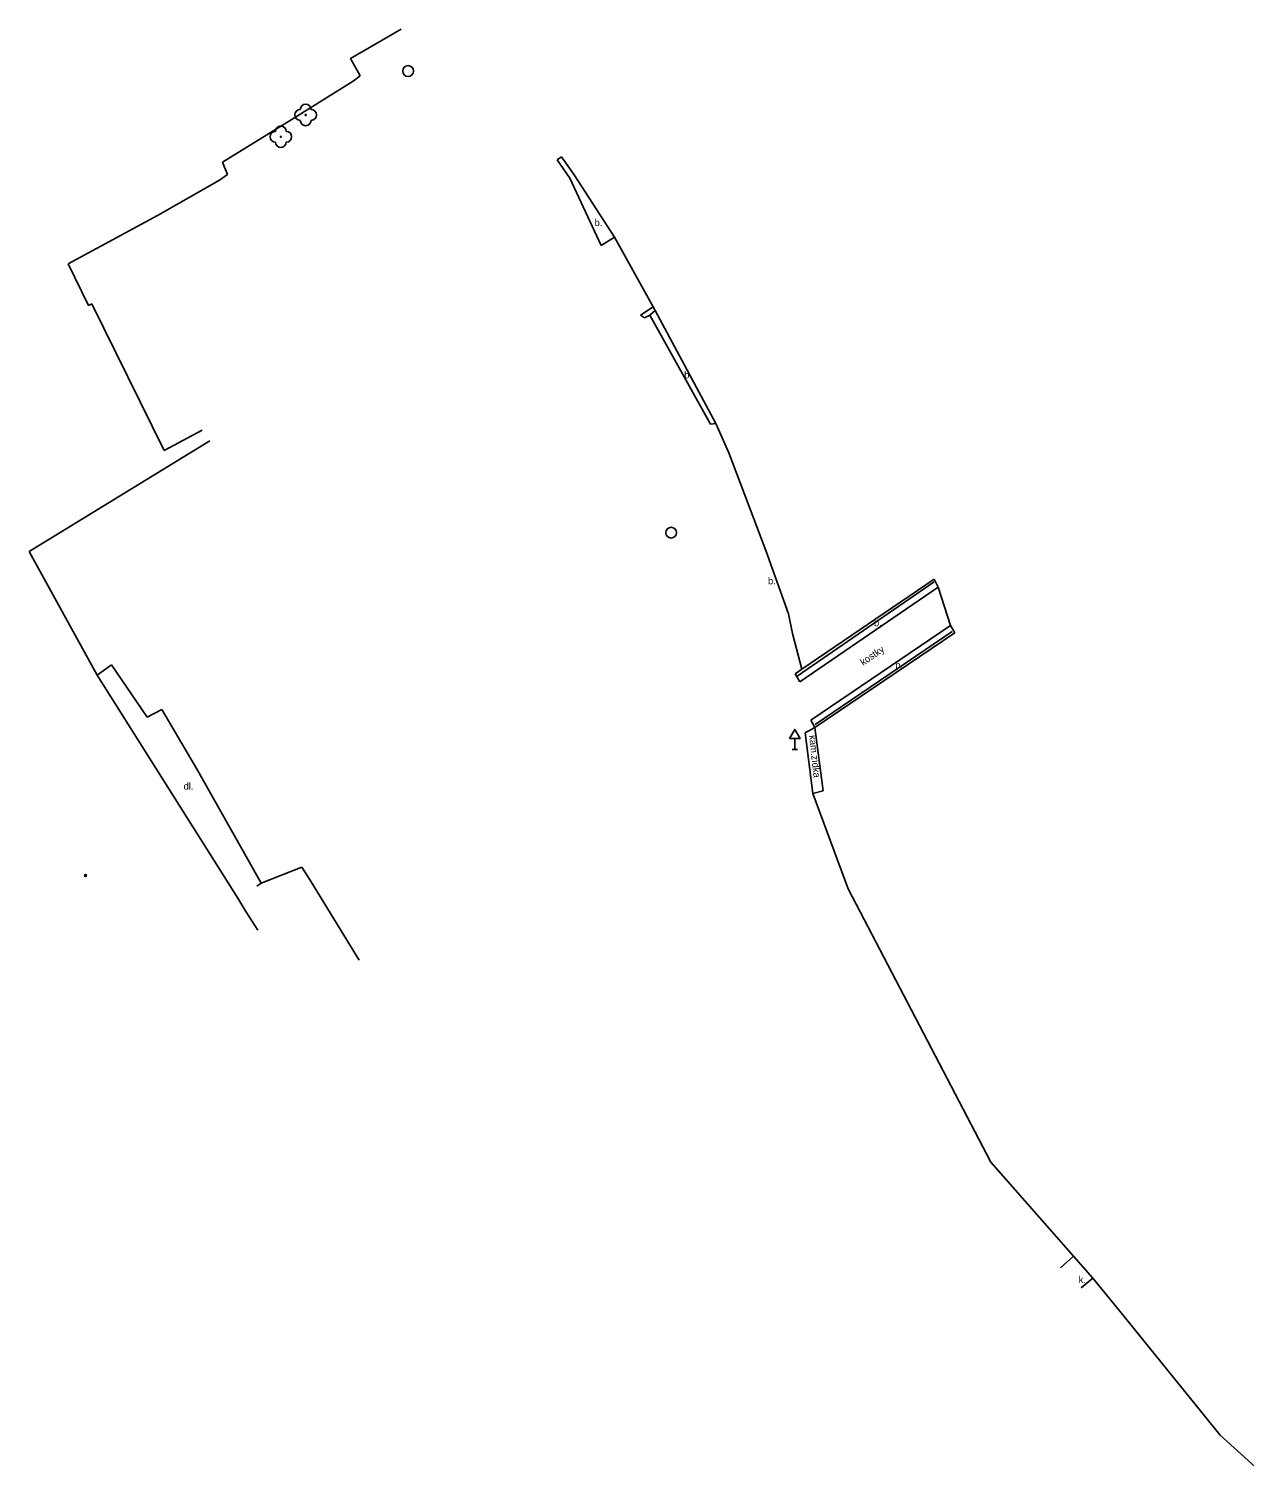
# Model space of a CAD drawing. Extents: x -639371 to -639058, y -1138650 to -1138362.
# Drawn here: x -639325.4 to -639212.8, y -1138496.9 to -1138362.2 of the extents above; entities that cross this region are included whole.
import ezdxf

# ---------------------------------------------------------------- set-up
doc = ezdxf.new("R2010")
doc.units = 0
for name, color, linetype in [('Vrstva 10', 7, 'Continuous'), ('Vrstva 11', 7, 'Continuous'), ('Vrstva 14', 7, 'Continuous'), ('Vrstva 22', 7, 'Continuous'), ('Vrstva 27', 7, 'Continuous'), ('Vrstva 34', 7, 'Continuous'), ('Vrstva 39', 7, 'Continuous'), ('Vrstva 40', 7, 'Continuous'), ('Vrstva 5', 7, 'Continuous'), ('Vrstva 7', 7, 'Continuous'), ('Vrstva 9', 7, 'Continuous')]:
    doc.layers.add(name, color=color, linetype=linetype)

msp = doc.modelspace()

# ---------------------------------------------------------------- linework, layer by layer
at = {"layer": 'Vrstva 10'}
for p, q in [((-639290.95, -1138362.19), (-639295.64, -1138364.92)), ((-639295.64, -1138364.92), (-639294.74, -1138366.53)), ((-639294.74, -1138366.53), (-639295.4, -1138367.02)), ((-639241.17, -1138413.92), (-639240.05, -1138417.48)), ((-639300.14, -1138439.85), (-639299.29, -1138441.23)), ((-639299.29, -1138441.23), (-639295.66, -1138447.12)), ((-639295.66, -1138447.12), (-639294.83, -1138448.47))]:
    msp.add_line(p, q, dxfattribs=at)
at = {"layer": 'Vrstva 11'}
for p, q in [((-639307.03, -1138375.67), (-639307.49, -1138374.52)), ((-639276.07, -1138374.04), (-639276.47, -1138374.3)), ((-639275.32, -1138376.02), (-639276.47, -1138374.3)), ((-639274.91, -1138375.71), (-639276.07, -1138374.04)), ((-639307.78, -1138376.2), (-639307.03, -1138375.67)), ((-639272.42, -1138382.24), (-639275.32, -1138376.02)), ((-639271.17, -1138381.48), (-639274.91, -1138375.71)), ((-639321.79, -1138383.96), (-639313.53, -1138379.48)), ((-639271.17, -1138381.48), (-639272.42, -1138382.24)), ((-639319.92, -1138387.81), (-639321.79, -1138383.96)), ((-639319.6, -1138387.65), (-639319.92, -1138387.81)), ((-639312.9, -1138401.25), (-639319.6, -1138387.65)), ((-639268.76, -1138388.69), (-639267.59, -1138387.92)), ((-639267.91, -1138388.7), (-639267.39, -1138388.28)), ((-639268.76, -1138388.69), (-639268.38, -1138388.94)), ((-639268.38, -1138388.94), (-639267.91, -1138388.7)), ((-639262.27, -1138398.82), (-639267.91, -1138388.7)), ((-639309.37, -1138399.37), (-639312.9, -1138401.25)), ((-639261.77, -1138398.73), (-639262.27, -1138398.82)), ((-639325.42, -1138410.61), (-639308.66, -1138400.34)), ((-639254, -1138422.69), (-639241.17, -1138413.92)), ((-639241.56, -1138413.16), (-639253.8, -1138421.51)), ((-639241.17, -1138413.92), (-639241.56, -1138413.16)), ((-639252.99, -1138426.23), (-639240.05, -1138417.48)), ((-639252.61, -1138426.93), (-639239.64, -1138418.16)), ((-639239.64, -1138418.16), (-639240.05, -1138417.48)), ((-639319.12, -1138422.06), (-639317.78, -1138421.11)), ((-639317.78, -1138421.11), (-639314.48, -1138425.96)), ((-639253.8, -1138421.51), (-639254.42, -1138421.94)), ((-639254.42, -1138421.94), (-639254, -1138422.69)), ((-639314.48, -1138425.96), (-639313.11, -1138425.26)), ((-639313.11, -1138425.26), (-639309.8, -1138430.87)), ((-639252.61, -1138426.93), (-639252.99, -1138426.23)), ((-639253.51, -1138427.41), (-639252.61, -1138426.93)), ((-639252.78, -1138433.03), (-639253.51, -1138427.41)), ((-639251.85, -1138432.8), (-639252.61, -1138426.93)), ((-639309.8, -1138430.87), (-639304.91, -1138439.58)), ((-639252.78, -1138433.03), (-639251.85, -1138432.8)), ((-639304.91, -1138439.58), (-639303.92, -1138441.35)), ((-639303.92, -1138441.35), (-639302.03, -1138440.6)), ((-639302.03, -1138440.6), (-639300.14, -1138439.85)), ((-639303.92, -1138441.35), (-639304.32, -1138441.61)), ((-639228.63, -1138475.93), (-639229.85, -1138477)), ((-639226.86, -1138477.95), (-639228.63, -1138475.93)), ((-639227.92, -1138478.85), (-639226.86, -1138477.95))]:
    msp.add_line(p, q, dxfattribs=at)
at = {"layer": 'Vrstva 14'}
for p, q in [((-639249.53, -1138441.86), (-639252.78, -1138433.03)), ((-639242.92, -1138454.55), (-639249.53, -1138441.86)), ((-639236.3, -1138467.2), (-639242.92, -1138454.55)), ((-639228.63, -1138475.93), (-639236.3, -1138467.2)), ((-639224.33, -1138481.02), (-639226.86, -1138477.95)), ((-639215.05, -1138492.49), (-639224.33, -1138481.02)), ((-639210.16, -1138496.93), (-639215.05, -1138492.49))]:
    msp.add_line(p, q, dxfattribs=at)
at = {"layer": 'Vrstva 22'}
for centre in [(-639299.79, -1138370.15), (-639302.09, -1138372.17)]:
    msp.add_circle(centre, 0.05, dxfattribs=at)
for centre, start, end in [((-639300.29, -1138370.15), 90, 270), ((-639299.79, -1138369.65), 0, 180), ((-639299.29, -1138370.15), 270, 90), ((-639299.79, -1138370.65), 180, 0), ((-639302.59, -1138372.17), 90, 270), ((-639302.09, -1138371.67), 0, 180), ((-639301.59, -1138372.17), 270, 90), ((-639302.09, -1138372.67), 180, 0)]:
    msp.add_arc(centre, 0.5, start, end, dxfattribs=at)
at = {"layer": 'Vrstva 27'}
for centre in [(-639290.3, -1138366.08), (-639265.92, -1138408.86)]:
    msp.add_circle(centre, 0.5, dxfattribs=at)
at = {"layer": 'Vrstva 34'}
for p, q in [((-639254.72, -1138428.97), (-639254.22, -1138428.97)), ((-639254.47, -1138427.95), (-639254.47, -1138428.97))]:
    msp.add_line(p, q, dxfattribs=at)
msp.add_lwpolyline([(-639254.97, -1138427.95), (-639253.97, -1138427.95), (-639254.47, -1138427.09)], close=True, dxfattribs=at)
at = {"layer": 'Vrstva 39'}
for radius in [0.09, 0.0398]:
    msp.add_circle((-639320.19, -1138440.64), radius, dxfattribs=at)
at = {"layer": 'Vrstva 5'}
for p, q in [((-639325.42, -1138410.61), (-639319.12, -1138422.06)), ((-639319.12, -1138422.06), (-639306.09, -1138442.75)), ((-639306.09, -1138442.75), (-639305.32, -1138443.96)), ((-639305.32, -1138443.96), (-639304.22, -1138445.71))]:
    msp.add_line(p, q, dxfattribs=at)
at = {"layer": 'Vrstva 7'}
for p, q in [((-639301.13, -1138370.59), (-639295.4, -1138367.02)), ((-639307.49, -1138374.52), (-639301.13, -1138370.59)), ((-639313.53, -1138379.48), (-639307.78, -1138376.2)), ((-639271.17, -1138381.48), (-639267.59, -1138387.92)), ((-639267.39, -1138388.28), (-639267.59, -1138387.92)), ((-639267.39, -1138388.28), (-639261.77, -1138398.73)), ((-639261.77, -1138398.73), (-639260.59, -1138401.47)), ((-639260.59, -1138401.47), (-639257.16, -1138410.51)), ((-639257.16, -1138410.51), (-639255.05, -1138416.38)), ((-639255.05, -1138416.38), (-639254.68, -1138418.22)), ((-639254.68, -1138418.22), (-639253.8, -1138421.51))]:
    msp.add_line(p, q, dxfattribs=at)
at = {"layer": 'Vrstva 9'}
for p, q in [((-639254.24, -1138422.17), (-639241.56, -1138413.43)), ((-639252.59, -1138426.63), (-639239.88, -1138418.01))]:
    msp.add_line(p, q, dxfattribs=at)

# ---------------------------------------------------------------- texts
at = {"layer": 'Vrstva 40'}
for s, p in [('b.', (-639273.02, -1138380.45)), ('b.', (-639264.72, -1138394.56)), ('b.', (-639256.95, -1138413.65)), ('b.', (-639247.13, -1138417.53)), ('b.', (-639245.15, -1138421.45)), ('dl.', (-639311.1, -1138432.68)), ('k.', (-639228.16, -1138478.4))]:
    msp.add_text(s, height=0.65, dxfattribs=at).set_placement(p)
for s, rotation, p in [('kostky', 34.3547, (-639248.13, -1138421.21)), ('kam.zídka', 276.0725, (-639253.14, -1138427.66))]:
    msp.add_text(s, height=0.65, rotation=rotation, dxfattribs=at).set_placement(p)

doc.saveas('drawing.dxf')
